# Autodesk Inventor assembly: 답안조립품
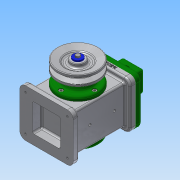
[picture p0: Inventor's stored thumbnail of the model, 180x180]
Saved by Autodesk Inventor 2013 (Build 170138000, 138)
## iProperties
Created: 2017-08
Part Number: 답안조립품
Document SubType Name: Assembly
Designer: Administrator
Author: Administrator
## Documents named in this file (18)
- C:\Users\Administrator\Desktop\470808V1016\답안조립품.iam
- C:\Users\Administrator\Desktop\470808V1016\본체.ipt
- C:\Users\Administrator\Desktop\470808V1016\E-링.ipt
- C:\Users\Administrator\Desktop\470808V1016\V-벨트풀리.ipt
- C:\Users\Administrator\Desktop\470808V1016\덮개.ipt
- C:\Users\Administrator\Desktop\470808V1016\뒤커버.ipt
- C:\Users\Administrator\Desktop\470808V1016\링크.ipt
- C:\Users\Administrator\Desktop\470808V1016\베어링 17 x 40 x 12.ipt
- C:\Users\Administrator\Desktop\470808V1016\볼트 M4 x 8.ipt
- C:\Users\Administrator\Desktop\470808V1016\볼트 M4 x 10.ipt
- C:\Users\Administrator\Desktop\470808V1016\슬라이더.ipt
- C:\Users\Administrator\Desktop\470808V1016\앞커버.ipt
- C:\Users\Administrator\Desktop\470808V1016\오일 실 17 30 8.ipt
- C:\Users\Administrator\Desktop\470808V1016\와셔 4x16.ipt
- C:\Users\Administrator\Desktop\470808V1016\클레비스 핀 6 x 22.ipt
- 클레비스 핀 6 x 22.ipt
- C:\Users\Administrator\Desktop\470808V1016\키 4 x 4 x 12.ipt
- C:\Users\Administrator\Desktop\470808V1016\편심축.ipt
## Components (2 placed, 2 different names)
1. E-링:1
2. V-벨트풀리:1
